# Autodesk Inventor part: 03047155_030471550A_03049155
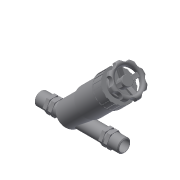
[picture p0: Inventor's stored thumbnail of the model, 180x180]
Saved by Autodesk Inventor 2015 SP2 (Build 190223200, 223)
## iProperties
Created: 2017-05
Part Number: 03047155_030471550A_03049155
Material: Generic
Description: PLASSON ANGLE SEAT VALVE 1.1/2"-1.1/2"
Document SubType Name: Modeling
Designer: KIM
Density: 1 g/cm^3
Appearance: Default
Author: KIM
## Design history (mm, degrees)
derived "03049.ipt"
feature "Solid1::03049.ipt"
tag "TaggingFeature1"
body "Solid1"
other parameters: "d1" = 41.91, "d2" = 46, "d3" = 33.528, "d4" = 22, "d5" = 22, "d8" = 2, "d12" = 0, "d15" = 4, "d16" = 0, "d17" = 53.46, "d18" = 6.48, "d19" = 178.2, "d20" = 60.75, "d21" = 135 deg, "d22" = 68.85, "d23" = 32.4, "d24" = 76.95, "d25" = 19.44, "d26" = 90 deg, "d27" = 56.7, "d28" = 70 deg, "d29" = 24.3, "d30" = 19.44, "d31" = 24.3, "d32" = 81, "d33" = 56.7, "d34" = 135 deg, "d35" = 2, "d36" = 162, "d40" = 1.8, "d41" = 1, "d42" = 2, "d43" = 5.4, "d44" = 5.4, "d46" = 0, "d48" = 360 deg, "d50" = 0.9, "d51" = 0.9, "d53" = 360 deg, "d69" = 68.85, "d70" = 5.4, "d71" = 5.4, "d72" = 10.8, "d74" = 0, "d75" = 0.9, "d77" = 360 deg, "d80" = 74.6415, "d81" = 7.2, "d82" = 3.6, "d83" = 29.16, "d84" = 0, "d86" = 360 deg, "d88" = 1.8, "R_" = 41.91, "E_" = 46, "l_2" = 22, "d67" = 81, "d68" = 56.7, "d79" = 76.95
